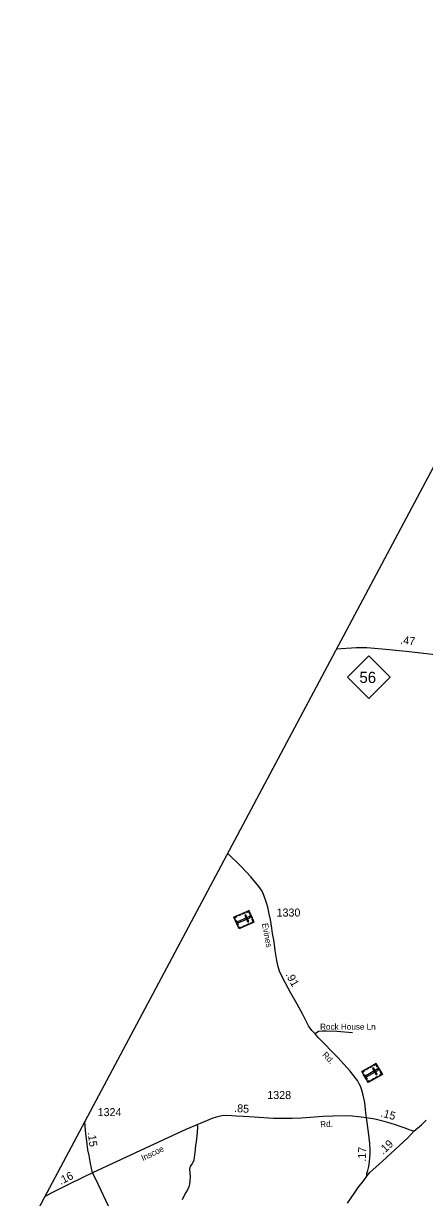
# Model space of a CAD drawing. Extents: x 2220236 to 2384410, y 720751 to 894131.
# Drawn here: x 2267477 to 2273739, y 846519 to 864850 of the extents above; entities that cross this region are included whole.
import ezdxf

# ---------------------------------------------------------------- set-up
doc = ezdxf.new("R2010")
doc.units = 0
doc.layers.add('Default', color=7, linetype='Continuous')

msp = doc.modelspace()

# ---------------------------------------------------------------- linework, layer by layer
at = {"layer": 'Default'}
for points in [[(2293118, 894131), (2291904, 891776), (2258822, 829665), (2255410, 823324), (2242089, 797599), (2231460, 775981), (2225011, 762953), (2220576, 753519)], [(2272362, 855087), (2272679, 855106), (2272838, 855105), (2273078, 855084), (2273451, 855050), (2273633, 855029), (2273858, 855001), (2273983, 854987), (2274089, 854978), (2274168, 854974), (2274247, 854972), (2274346, 854972), (2274469, 854976), (2274599, 854990), (2274706, 855013), (2274770, 855026), (2274803, 855038), (2274832, 855048)], [(2272834, 847762), (2272816, 847889), (2272806, 848003), (2272782, 848117), (2272761, 848196), (2272738, 848258), (2272720, 848295), (2272693, 848344), (2272652, 848400), (2272579, 848494), (2272387, 848703), (2272084, 849010), (2272032, 849073), (2271982, 849127), (2271929, 849202), (2271884, 849285), (2271840, 849376), (2271751, 849539), (2271654, 849708), (2271525, 849942), (2271477, 850053), (2271455, 850120), (2271431, 850221), (2271407, 850375), (2271396, 850468), (2271385, 850541), (2271367, 850643), (2271357, 850725), (2271336, 850860), (2271313, 850950), (2271290, 851055), (2271266, 851137), (2271235, 851225), (2271203, 851305), (2271151, 851378), (2271029, 851525), (2270874, 851686), (2270662, 851895)], [(2272613, 849093), (2272371, 849111), (2272201, 849115), (2272143, 849116), (2272085, 849111), (2272066, 849100), (2272032, 849073)], [(2268555, 846907), (2268524, 847048), (2268501, 847174), (2268484, 847266), (2268465, 847397), (2268443, 847562), (2268435, 847713)], [(2272834, 847762), (2272751, 847776), (2272570, 847793), (2272306, 847789), (2272158, 847782), (2271818, 847758), (2271676, 847751), (2271583, 847752), (2271493, 847753), (2271383, 847754), (2271002, 847778), (2270910, 847782), (2270799, 847790), (2270728, 847793), (2270645, 847799), (2270573, 847794), (2270508, 847779), (2270432, 847756), (2270014, 847581), (2269370, 847283), (2268555, 846907)], [(2270188, 847661), (2270192, 847625), (2270191, 847535), (2270176, 847387), (2270165, 847335), (2270156, 847268), (2270148, 847188), (2270139, 847102), (2270109, 847046), (2270081, 847009), (2270072, 846960), (2270078, 846845), (2270074, 846776), (2270069, 846728), (2270059, 846688), (2270036, 846640), (2270010, 846600), (2269977, 846532), (2269957, 846484)], [(2273571, 847555), (2273501, 847576), (2273439, 847602), (2273373, 847622), (2273286, 847652), (2273216, 847676), (2273107, 847705), (2272961, 847741), (2272834, 847762)], [(2272837, 846851), (2272839, 846893), (2272852, 846942), (2272870, 847006), (2272880, 847075), (2272886, 847149), (2272889, 847197), (2272891, 847259), (2272886, 847361), (2272862, 847538), (2272834, 847762)], [(2273571, 847555), (2273692, 847656), (2273764, 847725)], [(2272837, 846851), (2272886, 846911), (2273076, 847083), (2273346, 847333), (2273478, 847453), (2273571, 847555)], [(2268555, 846907), (2268406, 846833), (2268178, 846724), (2267911, 846589), (2267805, 846531)], [(2268842, 846307), (2268605, 846807), (2268555, 846907)], [(2272538, 846429), (2272643, 846583), (2272704, 846675), (2272791, 846785), (2272837, 846851)]]:
    msp.add_lwpolyline(points, dxfattribs=at)
for points in [[(2272536, 854643), (2272869, 854976), (2273202, 854643), (2272869, 854310)], [(2270998, 850999), (2271076, 850816), (2270843, 850716), (2270764, 850898)], [(2270828, 850926), (2270868, 850943), (2270872, 850933), (2270832, 850916)], [(2270890, 850953), (2270929, 850970), (2270934, 850959), (2270894, 850942)], [(2270958, 850982), (2270962, 850972), (2270992, 850984), (2271008, 850947), (2271018, 850952), (2270998, 850999)], [(2270777, 850868), (2270787, 850873), (2270779, 850893), (2270816, 850909), (2270811, 850919), (2270764, 850898)], [(2270797, 850850), (2270831, 850772), (2270820, 850768), (2270787, 850846)], [(2271014, 850888), (2271006, 850905), (2270820, 850824), (2270828, 850807)], [(2270905, 850755), (2270944, 850772), (2270949, 850761), (2270909, 850744)], [(2270951, 850935), (2270934, 850927), (2270981, 850819), (2270998, 850827)], [(2270965, 850781), (2271005, 850798), (2271009, 850787), (2270970, 850770)], [(2271027, 850931), (2271047, 850884), (2271037, 850879), (2271016, 850927)], [(2271037, 850799), (2271032, 850810), (2271062, 850822), (2271046, 850860), (2271056, 850864), (2271076, 850816)], [(2270830, 850746), (2270840, 850751), (2270849, 850730), (2270886, 850746), (2270890, 850736), (2270843, 850716)], [(2272980, 848614), (2273081, 848442), (2272861, 848314), (2272760, 848486)], [(2272879, 848555), (2272916, 848577), (2272922, 848567), (2272884, 848545)], [(2272943, 848592), (2272948, 848583), (2272976, 848599), (2272997, 848564), (2273006, 848569), (2272980, 848614)], [(2272777, 848457), (2272787, 848463), (2272776, 848482), (2272811, 848502), (2272805, 848512), (2272760, 848486)], [(2272799, 848442), (2272842, 848369), (2272832, 848363), (2272789, 848436)], [(2272821, 848521), (2272858, 848543), (2272864, 848533), (2272826, 848511)], [(2273010, 848505), (2273000, 848521), (2272825, 848419), (2272835, 848403)], [(2272917, 848360), (2272955, 848382), (2272961, 848372), (2272923, 848350)], [(2272942, 848545), (2272926, 848535), (2272985, 848434), (2273001, 848443)], [(2272974, 848393), (2273012, 848415), (2273017, 848405), (2272980, 848384)], [(2273017, 848550), (2273044, 848506), (2273034, 848500), (2273008, 848544)], [(2273043, 848420), (2273037, 848430), (2273065, 848446), (2273045, 848481), (2273054, 848487), (2273081, 848442)], [(2272844, 848342), (2272854, 848348), (2272865, 848329), (2272900, 848350), (2272906, 848340), (2272861, 848314)]]:
    msp.add_lwpolyline(points, close=True, dxfattribs=at)

# ---------------------------------------------------------------- texts
for s, height, rotation, p in [('.47', 125, 353.5023, (2273355, 855167)), ('Evines', 95, 280.4366, (2271200, 850794)), ('.91', 125, 298.8232, (2271566, 849999)), ('Rd.', 95, 313.7044, (2272136, 848739)), ('.85', 125, 356.1837, (2270764, 847855)), ('.15', 125, 344.867, (2273044, 847787)), ('Rd.', 95, 2.8256, (2272113, 847615)), ('.15', 125, 277.1552, (2268480, 847535)), ('Inscoe', 95, 25.3505, (2269342, 847087)), ('.17', 125, 88.8015, (2272824, 847077)), ('.19', 125, 42.8739, (2273093, 847183)), ('.16', 125, 26.7454, (2268060, 846715))]:
    msp.add_text(s, height=height, rotation=rotation, dxfattribs=at).set_placement(p)
for s, height, p in [('56', 175, (2272723, 854553)), ('1330', 125, (2271429, 850906)), ('Rock House Ln', 95, (2272109, 849139)), ('1328', 125, (2271284, 848057)), ('1324', 125, (2268635, 847790))]:
    msp.add_text(s, height=height, dxfattribs=at).set_placement(p)

doc.saveas('drawing.dxf')
